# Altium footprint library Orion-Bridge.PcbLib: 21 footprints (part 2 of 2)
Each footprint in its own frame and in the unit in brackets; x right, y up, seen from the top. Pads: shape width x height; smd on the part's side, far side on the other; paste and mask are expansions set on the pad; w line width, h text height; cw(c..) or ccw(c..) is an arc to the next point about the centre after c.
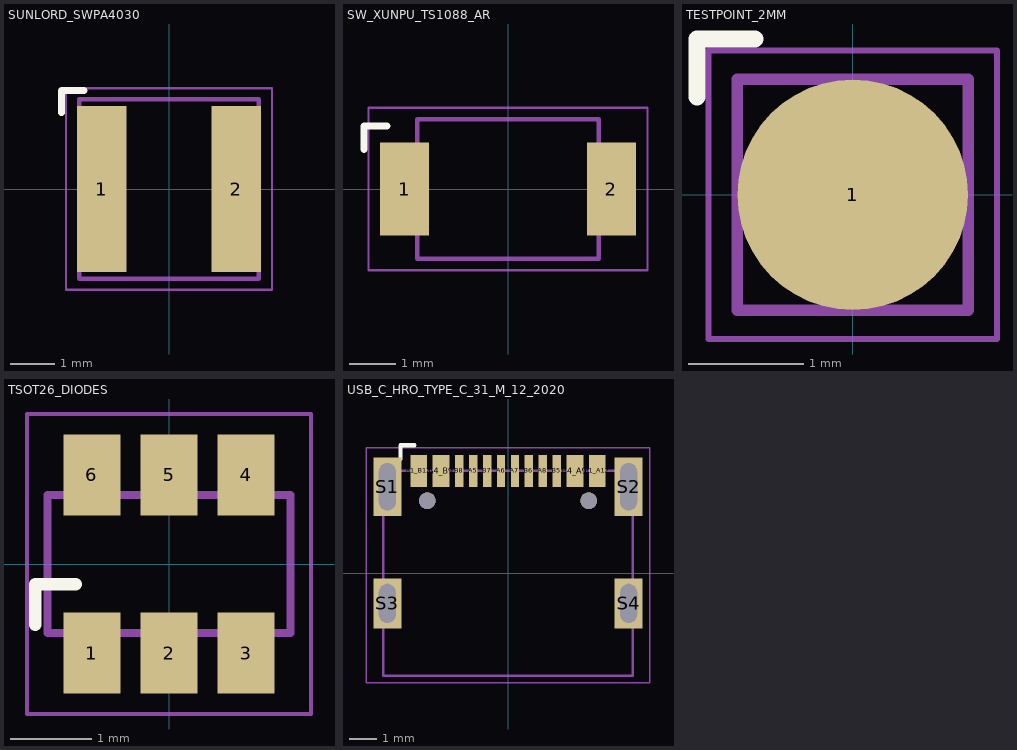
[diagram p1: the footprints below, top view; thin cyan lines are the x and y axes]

## SUNLORD_SWPA4030 [mm] "Sunlord SWPA datasheet2025-05-08 p2 recommended SWPA4030S pattern: gap1.9, padwidth1.1, padheight3.7."
height 3
pads (2):
  rect 1.1x3.7 smd: 1(-1.5,0) 2(1.5,0)
Top Overlay:
  lines w0.15: -2.4,1.7 -2.4,2.2 -1.9,2.2
Component bodies:
  lines w0.1: -2,-2 2,-2 2,2 -2,2 -2,-2
Courtyards:
  lines w0.05: -2.3,-2.25 2.3,-2.25 2.3,2.25 -2.3,2.25 -2.3,-2.25
3D body: height 3, standoff 0.1, extent -2,-2 2,2
3D body: height 3.02, standoff 3, extent -1.6,-1.6 1.6,1.6
3D body: height 0.18, standoff 0.03, extent -1.94,-1.48 -1.06,1.48
3D body: height 0.18, standoff 0.03, extent 1.06,-1.48 1.94,1.48

## SW_XUNPU_TS1088_AR [mm] "XUNPU TS-1088-ARXXXXXX manufacturer drawing: outer width5.50, inner gap3.40, padheight2.00; two terminals, no locating posts."
height 2
pads (2):
  rect 1.05x2 smd: 1(-2.225,0) 2(2.225,0)
Top Overlay:
  lines w0.15: -3.1,0.85 -3.1,1.35 -2.6,1.35
Component bodies:
  lines w0.1: -1.95,-1.5 1.95,-1.5 1.95,1.5 -1.95,1.5 -1.95,-1.5
Courtyards:
  lines w0.05: -3,-1.75 3,-1.75 3,1.75 -3,1.75 -3,-1.75
3D body: height 1.2, standoff 0.12, extent -1.95,-1.5 1.95,1.5
3D body: height 1.5, standoff 1.2, extent -1.9,-1.45 1.9,1.45
3D body: height 2, standoff 1.5, extent -0.9,-0.9 0.9,0.9
3D body: height 0.2, standoff 0.03, extent -2.675,-0.65 -1.775,0.65
3D body: height 0.2, standoff 0.03, extent 1.775,-0.65 2.675,0.65

## TESTPOINT_2MM [mm] "2 mm exposed top-copper test pad; no paste"
pads (1):
  round 2 smd: 1(0,0)
Top Overlay:
  lines w0.15: -1.35,0.85 -1.35,1.35 -0.85,1.35
Component bodies:
  lines w0.1: -1,-1 1,-1 1,1 -1,1 -1,-1
Courtyards:
  lines w0.05: -1.25,-1.25 1.25,-1.25 1.25,1.25 -1.25,1.25 -1.25,-1.25
3D body: height 0.06, standoff 0.03, extent -1,-1 1,1

## TSOT26_DIODES [mm] "Diodes DS41326 Rev3-2 p17 suggested TSOT26 copper: X=.70,Y=1.00,Y1=3.20 total span,C=.95. Top view: pin1 lower-left; pin4 upper-right."
height 1
pads (6):
  rect 0.7x1 smd: 1(-0.95,-1.1) 2(0,-1.1) 3(0.95,-1.1) 4(0.95,1.1) 5(0,1.1) 6(-0.95,1.1)
Top Overlay:
  lines w0.15: -1.65,-0.75 -1.65,-0.25 -1.15,-0.25
Component bodies:
  lines w0.1: -1.5,-0.85 1.5,-0.85 1.5,0.85 -1.5,0.85 -1.5,-0.85
Courtyards:
  lines w0.05: -1.75,-1.85 1.75,-1.85 1.75,1.85 -1.75,1.85 -1.75,-1.85
3D body: height 1, standoff 0.08, extent -1.5,-0.85 1.5,0.85
3D body: height 0.22, standoff 0.03, extent -1.175,-1.35 -0.725,-0.55
3D body: height 0.22, standoff 0.03, extent -0.225,-1.35 0.225,-0.55
3D body: height 0.22, standoff 0.03, extent 0.725,-1.35 1.175,-0.55
3D body: height 0.22, standoff 0.03, extent 0.725,0.55 1.175,1.35
3D body: height 0.22, standoff 0.03, extent -0.225,0.55 0.225,1.35
3D body: height 0.22, standoff 0.03, extent -1.175,0.55 -0.725,1.35
3D body: height 1.01, standoff 1, extent -1.03,-0.64 -0.77,-0.38

## USB_C_HRO_TYPE_C_31_M_12_2020 [mm] "HRO drawing dated2020-12-08 downloaded via JLC C165948. NOT older2018 KiCad footprint: updated front slots1.4, padwidth centres3.20/2.40 and padheight1.14. Body envelope3D is nominal. Shield copper enlarged by0.05mm peredge from manufacturer recommendation to provide0.20mm annular ring; drills unchanged."
height 3.26
pads (18):
  rect 0.6x1.14 smd: A1_B12(-3.2,3.67) A4_B9(-2.4,3.67) B1_A12(3.2,3.67) B4_A9(2.4,3.67)
  rect 0.3x1.14 smd: A5(-1.25,3.67) A6(-0.25,3.67) A7(0.25,3.67) A8(1.25,3.67) B5(1.75,3.67) B6(0.75,3.67) B7(-0.75,3.67) B8(-1.75,3.67)
  rect 1x2.1 hole 0.6 slot 1.7 at 90 deg paste-10: S1(-4.325,3.1) S2(4.325,3.1)
  rect 1x1.8 hole 0.6 slot 1.4 at 90 deg paste-10: S3(-4.325,-1.08) S4(4.325,-1.08)
  round 0.6 hole 0.6 unplated paste-10: ""(-2.89,2.6) ""(2.89,2.6)
Top Overlay:
  lines w0.15: -3.85,4.09 -3.85,4.59 -3.35,4.59
Component bodies:
  lines w0.1: -4.47,-3.675 4.47,-3.675 4.47,3.675 -4.47,3.675 -4.47,-3.675
Courtyards:
  lines w0.05: -5.075,-3.925 5.075,-3.925 5.075,4.49 -5.075,4.49 -5.075,-3.925
3D body: height 0.27, standoff 0.08, extent -4.47,-3.675 4.47,3.675
3D body: height 3.26, standoff 3.05, extent -4.47,-3.675 4.47,3.675
3D body: height 3.05, standoff 0.27, extent -4.47,-3.675 -4.27,3.675
3D body: height 3.05, standoff 0.27, extent 4.27,-3.675 4.47,3.675
3D body: height 3.03, standoff 0.28, extent -4.27,2.875 4.27,3.675
3D body: height 1.76, standoff 1.4, extent -3.345,-3.1 3.345,1.6
3D body: height 1.78, standoff 1.76, extent -2.86,-2.55 -2.64,0.25
3D body: height 1.78, standoff 1.76, extent -2.36,-2.55 -2.14,0.25
3D body: height 1.78, standoff 1.76, extent -1.86,-2.55 -1.64,0.25
3D body: height 1.78, standoff 1.76, extent -1.36,-2.55 -1.14,0.25
3D body: height 1.78, standoff 1.76, extent -0.86,-2.55 -0.64,0.25
3D body: height 1.78, standoff 1.76, extent -0.36,-2.55 -0.14,0.25
3D body: height 1.78, standoff 1.76, extent 0.14,-2.55 0.36,0.25
3D body: height 1.78, standoff 1.76, extent 0.64,-2.55 0.86,0.25
3D body: height 1.78, standoff 1.76, extent 1.14,-2.55 1.36,0.25
3D body: height 1.78, standoff 1.76, extent 1.64,-2.55 1.86,0.25
3D body: height 1.78, standoff 1.76, extent 2.14,-2.55 2.36,0.25
3D body: height 1.78, standoff 1.76, extent 2.64,-2.55 2.86,0.25
3D body: height 0.22, standoff 0.03, extent -3.375,3.195 -3.025,4.145
3D body: height 0.22, standoff 0.03, extent -2.575,3.195 -2.225,4.145
3D body: height 0.22, standoff 0.03, extent -1.855,3.195 -1.645,4.145
3D body: height 0.22, standoff 0.03, extent -1.355,3.195 -1.145,4.145
3D body: height 0.22, standoff 0.03, extent -0.855,3.195 -0.645,4.145
3D body: height 0.22, standoff 0.03, extent -0.355,3.195 -0.145,4.145
3D body: height 0.22, standoff 0.03, extent 0.145,3.195 0.355,4.145
3D body: height 0.22, standoff 0.03, extent 0.645,3.195 0.855,4.145
3D body: height 0.22, standoff 0.03, extent 1.145,3.195 1.355,4.145
3D body: height 0.22, standoff 0.03, extent 1.645,3.195 1.855,4.145
3D body: height 0.22, standoff 0.03, extent 2.225,3.195 2.575,4.145
3D body: height 0.22, standoff 0.03, extent 3.025,3.195 3.375,4.145
3D body: height 0.5, standoff -1.3, extent -4.45,2.6 -4.2,3.6
3D body: height 0.5, standoff -1.3, extent 4.2,2.6 4.45,3.6
3D body: height 0.5, standoff -1.3, extent -4.45,-1.58 -4.2,-0.58
3D body: height 0.5, standoff -1.3, extent 4.2,-1.58 4.45,-0.58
